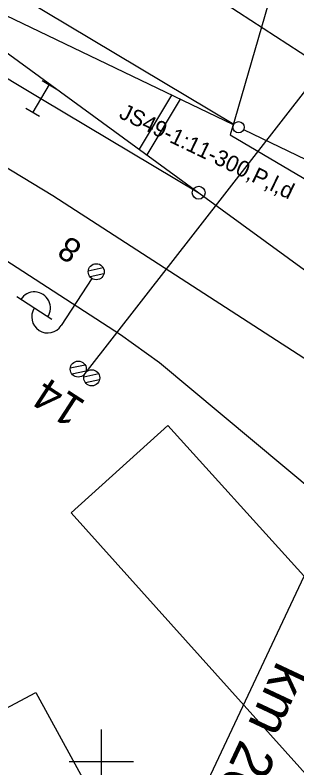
# Model space of a CAD drawing. Extents: x -800194 to -799078, y -1007177 to -1006597.
# Drawn here: x -799805.36 to -799787.82, y -1007000.4 to -1006953.52 of the extents above; entities that cross this region are included whole.
import ezdxf

# ---------------------------------------------------------------- set-up
doc = ezdxf.new("R2010")
doc.units = 0
for name, color, linetype in [('_návrh', 7, 'Continuous'), ('_popvyt', 7, 'Continuous'), ('Ramove udaje', 7, 'Continuous'), ('Vrstva 1', 7, 'Continuous'), ('Vrstva 11', 7, 'Continuous'), ('Vrstva 2', 7, 'Continuous'), ('Vrstva 23', 7, 'Continuous'), ('Vrstva 25', 7, 'Continuous'), ('Vrstva 3', 7, 'Continuous'), ('Vrstva 4', 7, 'Continuous'), ('Vrstva 49', 7, 'Continuous'), ('Vrstva 5', 7, 'Continuous'), ('Vrstva 55', 7, 'Continuous'), ('Vrstva 7', 7, 'Continuous')]:
    doc.layers.add(name, color=color, linetype=linetype)

msp = doc.modelspace()

# ---------------------------------------------------------------- linework, layer by layer
at = {"layer": '_návrh'}
for p, q in [((-799820.103, -1006945.483), (-799793.935, -1006964.581)), ((-799791.756, -1006960.321), (-799808.622, -1006950.239)), ((-799791.771, -1006960.349), (-799809.481, -1006951.835)), ((-799791.14, -1006960.652), (-799779.191, -1006966.397))]:
    msp.add_line(p, q, dxfattribs=at)
for points in [[(-799821.595, -1006948.007), (-799811.064, -1006954.324), (-799803.753, -1006958.707), (-799793.935, -1006964.581), (-799784.224, -1006971.671), (-799782.913, -1006972.63), (-799767.418, -1006984.719), (-799752.333, -1006998.173), (-799735.027, -1007015.997), (-799721.623, -1007030.81), (-799713.555, -1007039.726), (-799713.111, -1007040.218)], [(-799820.755, -1006954.001), (-799803.004, -1006964.743), (-799786.682, -1006975.322), (-799769.882, -1006987.807), (-799754.745, -1007000.643), (-799736.311, -1007017.261), (-799721.623, -1007030.81)]]:
    msp.add_lwpolyline(points, dxfattribs=at)
msp.add_circle((-799791.455, -1006960.501), 0.35, dxfattribs=at)
at = {"layer": 'Ramove udaje'}
for p, q in [((-799800, -1006998), (-799800, -1007002)), ((-799802, -1007000), (-799800, -1007000)), ((-799800, -1007000), (-799798, -1007000))]:
    msp.add_line(p, q, dxfattribs=at)
at = {"layer": 'Vrstva 1'}
msp.add_lwpolyline([(-799773.482, -1006996.72), (-799784.684, -1006984.939), (-799796.383, -1006975.181), (-799798.809, -1006973.435), (-799814.345, -1006963.355), (-799826.008, -1006956.394)], dxfattribs=at)
at = {"layer": 'Vrstva 11'}
for p, q in [((-799801.01, -1006975.832), (-799786.978, -1006957.812)), ((-799801.001, -1006975.309), (-799801.925, -1006975.506)), ((-799800.947, -1006975.681), (-799801.822, -1006975.868)), ((-799800.16, -1006975.857), (-799801.087, -1006976.054)), ((-799800.108, -1006976.229), (-799800.981, -1006976.415))]:
    msp.add_line(p, q, dxfattribs=at)
for centre in [(-799801.429, -1006975.56), (-799800.591, -1006976.104)]:
    msp.add_circle(centre, 0.5, dxfattribs=at)
at = {"layer": 'Vrstva 2'}
msp.add_circle((-799793.935, -1006964.581), 0.4, dxfattribs=at)
at = {"layer": 'Vrstva 23'}
for points in [[(-799795.856, -1006979.079), (-799779.728, -1006996.929), (-799785.824, -1007002.398), (-799801.87, -1006984.513), (-799795.856, -1006979.079)], [(-799797.881, -1007007.005), (-799803.933, -1007010.185), (-799810.13, -1006998.908), (-799804.077, -1006995.693), (-799797.881, -1007007.005)]]:
    msp.add_lwpolyline(points, dxfattribs=at)
at = {"layer": 'Vrstva 25'}
for p, q in [((-799799.875, -1006969.26), (-799800.811, -1006969.46)), ((-799799.832, -1006969.634), (-799800.693, -1006969.818)), ((-799800.585, -1006969.917), (-799802.489, -1006972.854)), ((-799803.076, -1006972.473), (-799805.258, -1006971.059))]:
    msp.add_line(p, q, dxfattribs=at)
msp.add_circle((-799800.313, -1006969.497), 0.5, dxfattribs=at)
for centre, start, end in [((-799804.16, -1006971.756), 326.3484, 147.7535), ((-799803.328, -1006972.31), 147.051, 327.051)]:
    msp.add_arc(centre, 1, start, end, dxfattribs=at)
at = {"layer": 'Vrstva 3'}
for p, q in [((-799803.668, -1006957.592), (-799802.81, -1006958.106)), ((-799803.239, -1006957.849), (-799804.267, -1006959.565)), ((-799804.696, -1006959.308), (-799803.838, -1006959.822))]:
    msp.add_line(p, q, dxfattribs=at)
at = {"layer": 'Vrstva 4'}
msp.add_line((-799796.383, -1006975.181), (-799798.809, -1006973.435), dxfattribs=at)
at = {"layer": 'Vrstva 49'}
msp.add_lwpolyline([(-799809.896, -1006941.363), (-799780.709, -1006960.303)], dxfattribs=at)
at = {"layer": 'Vrstva 5'}
msp.add_line((-799796.24, -1007007.322), (-799778.659, -1006969.886), dxfattribs=at)
at = {"layer": 'Vrstva 55'}
msp.add_lwpolyline([(-799785.23, -1006937.71), (-799791.69, -1006959.99), (-799791.97, -1006960.97), (-799746.76, -1006987.67), (-799745.68, -1006988.03), (-799733.28, -1006992.13)], dxfattribs=at)
at = {"layer": 'Vrstva 7'}
for p, q in [((-799795.627, -1006958.5), (-799797.645, -1006961.872)), ((-799795.084, -1006958.761), (-799797.158, -1006962.228)), ((-799796.379, -1006960.341), (-799796.379, -1006960.341))]:
    msp.add_line(p, q, dxfattribs=at)

# ---------------------------------------------------------------- texts
at = {"layer": '_popvyt'}
msp.add_text('      JS49-1:11-300,P,l,d', height=1, rotation=334.3251, dxfattribs=at).set_placement((-799800.968, -1006958.927))
at = {"layer": 'Vrstva 11'}
msp.add_text('14', height=2, rotation=147.0239, dxfattribs=at).set_placement((-799800.876, -1006977.628))
at = {"layer": 'Vrstva 25'}
msp.add_text('8', height=1.5, rotation=147.051, dxfattribs=at).set_placement((-799801.102, -1006967.811))
at = {"layer": 'Vrstva 5'}
msp.add_text('km 204,169', height=2.5, rotation=244.8436, dxfattribs=at).set_placement((-799789.022, -1006993.664))

doc.saveas('drawing.dxf')
